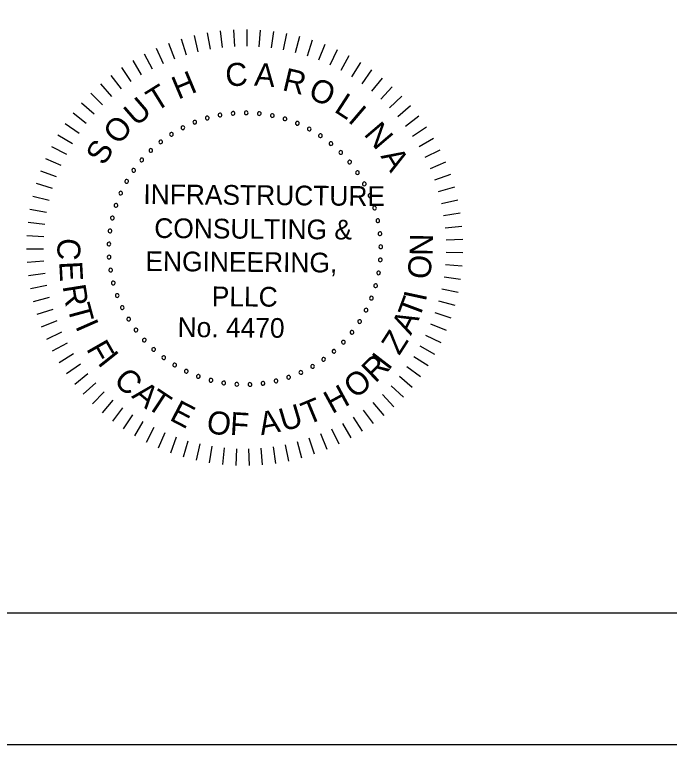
# Model space of a CAD drawing. Extents: x 2799.7 to 2896, y 515.2 to 573.9.
# Drawn here: x 2867.59 to 2874.21, y 515.22 to 522.61 of the extents above; entities that cross this region are included whole.
import ezdxf

# ---------------------------------------------------------------- set-up
doc = ezdxf.new("R2010")
doc.units = 0
for name, color, linetype in [('BR_BORDER LINES', 7, 'Continuous'), ('BR_TEXT', 7, 'Continuous'), ('Level 31', 7, 'Continuous')]:
    doc.layers.add(name, color=color, linetype=linetype)

msp = doc.modelspace()

# ---------------------------------------------------------------- linework, layer by layer
at = {"layer": 'BR_BORDER LINES'}
msp.add_line((2804.5816, 516.5558), (2894.3589, 516.5558), dxfattribs=at)
at = {"layer": 'BR_TEXT'}
for p, q in [((2869.6661, 522.4445), (2869.6854, 522.2758)), ((2869.8003, 522.4555), (2869.8093, 522.286)), ((2869.9349, 522.4584), (2869.9335, 522.2886)), ((2870.0694, 522.453), (2870.0577, 522.2836)), ((2870.2034, 522.4394), (2870.1813, 522.2711)), ((2869.2711, 522.3628), (2869.3208, 522.2004)), ((2869.4011, 522.3981), (2869.4407, 522.233)), ((2869.5329, 522.4253), (2869.5624, 522.2581)), ((2870.3362, 522.4177), (2870.304, 522.251)), ((2870.4675, 522.3879), (2870.4251, 522.2235)), ((2869.1436, 522.3197), (2869.2031, 522.1606)), ((2870.5968, 522.3502), (2870.5444, 522.1887)), ((2870.7235, 522.3047), (2870.6614, 522.1467)), ((2869.0189, 522.2689), (2869.088, 522.1137)), ((2870.8471, 522.2515), (2870.7755, 522.0976)), ((2868.78, 522.1449), (2868.8674, 521.9994)), ((2868.8976, 522.2105), (2868.976, 522.0599)), ((2870.9673, 522.1909), (2870.8865, 522.0416)), ((2868.6667, 522.0723), (2868.7628, 521.9323)), ((2871.0836, 522.1231), (2870.9938, 521.979)), ((2871.1956, 522.0483), (2871.0972, 521.9099)), ((2868.558, 521.9929), (2868.6625, 521.859)), ((2871.3027, 521.9668), (2871.1961, 521.8347)), ((2868.4544, 521.9069), (2868.5668, 521.7797)), ((2871.4048, 521.879), (2871.2902, 521.7536)), ((2868.3561, 521.8149), (2868.4761, 521.6947)), ((2871.5012, 521.7851), (2871.3793, 521.6669)), ((2868.2637, 521.717), (2868.3908, 521.6044)), ((2871.5918, 521.6855), (2871.4628, 521.575)), ((2868.1774, 521.6137), (2868.3111, 521.509)), ((2871.6761, 521.5805), (2871.5407, 521.4781)), ((2868.0976, 521.5053), (2868.2374, 521.409)), ((2871.7538, 521.4706), (2871.6124, 521.3766)), ((2868.0245, 521.3922), (2868.17, 521.3046)), ((2871.8248, 521.3562), (2871.6779, 521.271)), ((2867.9585, 521.2749), (2868.109, 521.1963)), ((2871.8886, 521.2376), (2871.7368, 521.1616)), ((2867.8997, 521.1538), (2868.0547, 521.0845)), ((2871.945, 521.1154), (2871.7889, 521.0487)), ((2867.8484, 521.0293), (2868.0074, 520.9696)), ((2871.9939, 520.99), (2871.834, 520.933)), ((2867.8048, 520.9019), (2867.9671, 520.8521)), ((2872.0351, 520.8618), (2871.872, 520.8146)), ((2867.7691, 520.7721), (2867.9341, 520.7323)), ((2872.0684, 520.7314), (2871.9027, 520.6942)), ((2867.7413, 520.6404), (2867.9085, 520.6107)), ((2872.0936, 520.5991), (2871.926, 520.5722)), ((2867.7216, 520.5072), (2867.8903, 520.4877)), ((2872.1108, 520.4656), (2871.9418, 520.4489)), ((2867.7101, 520.3731), (2867.8797, 520.3639)), ((2872.1198, 520.3313), (2871.9501, 520.3249)), ((2867.7068, 520.2385), (2867.8766, 520.2397)), ((2872.1206, 520.1967), (2871.9508, 520.2006)), ((2867.7117, 520.104), (2867.8811, 520.1155)), ((2872.1131, 520.0622), (2871.9439, 520.0766)), ((2867.7247, 519.97), (2867.8931, 519.9918)), ((2872.0975, 519.9285), (2871.9295, 519.9531)), ((2867.746, 519.837), (2867.9127, 519.8691)), ((2872.0738, 519.796), (2871.9076, 519.8308)), ((2867.7752, 519.7056), (2867.9397, 519.7478)), ((2872.042, 519.6652), (2871.8783, 519.7101)), ((2867.8125, 519.5763), (2867.9741, 519.6284)), ((2872.0023, 519.5365), (2871.8416, 519.5913)), ((2867.8575, 519.4494), (2868.0157, 519.5113)), ((2871.9549, 519.4106), (2871.7978, 519.475)), ((2867.9103, 519.3255), (2868.0643, 519.3969)), ((2871.8998, 519.2877), (2871.747, 519.3616)), ((2867.9704, 519.2051), (2868.1198, 519.2857)), ((2871.8374, 519.1684), (2871.6893, 519.2515)), ((2868.0378, 519.0885), (2868.182, 519.1782)), ((2871.7678, 519.0532), (2871.6251, 519.1452)), ((2868.1122, 518.9763), (2868.2507, 519.0746)), ((2871.6913, 518.9424), (2871.5545, 519.0429)), ((2868.1933, 518.8688), (2868.3255, 518.9753)), ((2871.6082, 518.8365), (2871.4778, 518.9451)), ((2868.2807, 518.7665), (2868.4062, 518.8809)), ((2871.5188, 518.7358), (2871.3952, 518.8522)), ((2868.3743, 518.6697), (2868.4926, 518.7915)), ((2871.4234, 518.6408), (2871.3072, 518.7645)), ((2868.4736, 518.5788), (2868.5842, 518.7076)), ((2871.3225, 518.5518), (2871.214, 518.6824)), ((2868.5782, 518.4941), (2868.6808, 518.6294)), ((2871.2162, 518.4691), (2871.1159, 518.606)), ((2868.6878, 518.4159), (2868.782, 518.5572)), ((2871.1052, 518.393), (2871.0134, 518.5358)), ((2868.802, 518.3446), (2868.8873, 518.4913)), ((2870.9897, 518.3238), (2870.9067, 518.472)), ((2868.9203, 518.2803), (2868.9965, 518.432)), ((2869.0423, 518.2234), (2869.1091, 518.3795)), ((2870.8702, 518.2618), (2870.7964, 518.4148)), ((2869.1675, 518.174), (2869.2248, 518.3339)), ((2870.6209, 518.1603), (2870.5664, 518.321)), ((2870.7471, 518.2072), (2870.6828, 518.3644)), ((2869.2956, 518.1324), (2869.3429, 518.2954)), ((2869.4259, 518.0986), (2869.4632, 518.2643)), ((2869.558, 518.0729), (2869.5852, 518.2405)), ((2870.2286, 518.0665), (2870.2042, 518.2345)), ((2870.3612, 518.0898), (2870.3266, 518.256)), ((2870.4922, 518.1211), (2870.4475, 518.2849)), ((2869.6915, 518.0552), (2869.7084, 518.2242)), ((2869.8258, 518.0458), (2869.8323, 518.2154)), ((2869.9604, 518.0445), (2869.9566, 518.2142)), ((2870.0948, 518.0514), (2870.0807, 518.2206))]:
    msp.add_line(p, q, dxfattribs=at)
for centre, start, end in [((2869.7956, 521.6102), 5.06529, 185.06529), ((2869.9284, 521.6153), 359.52683, 179.52683), ((2870.0611, 521.6075), 353.98837, 173.98837), ((2869.5346, 521.5619), 16.14222, 196.14222), ((2869.5346, 521.5619), 196.14222, 16.14222), ((2869.664, 521.5924), 10.60376, 190.60376), ((2869.664, 521.5924), 190.60376, 10.60376), ((2869.7956, 521.6102), 185.06529, 5.06529), ((2869.9284, 521.6153), 179.52683, 359.52683), ((2870.0611, 521.6075), 173.98837, 353.98837), ((2870.1924, 521.587), 168.44991, 348.44991), ((2870.1924, 521.587), 348.44991, 168.44991), ((2870.3211, 521.5538), 162.91145, 342.91145), ((2870.3211, 521.5538), 342.91145, 162.91145), ((2869.2878, 521.4643), 27.21914, 207.21914), ((2869.4088, 521.5191), 21.68068, 201.68068), ((2869.4088, 521.5191), 201.68068, 21.68068), ((2870.446, 521.5085), 157.37299, 337.37299), ((2870.446, 521.5085), 337.37299, 157.37299), ((2869.1725, 521.3981), 32.7576, 212.7576), ((2869.1725, 521.3981), 212.7576, 32.7576), ((2869.2878, 521.4643), 207.21914, 27.21914), ((2870.5659, 521.4512), 151.83453, 331.83453), ((2870.5659, 521.4512), 331.83453, 151.83453), ((2869.0642, 521.3211), 38.29606, 218.29606), ((2869.0642, 521.3211), 218.29606, 38.29606), ((2870.6797, 521.3827), 146.29606, 326.29606), ((2870.6797, 521.3827), 326.29606, 146.29606), ((2870.7864, 521.3035), 140.7576, 320.7576), ((2870.7864, 521.3035), 320.7576, 140.7576), ((2868.9639, 521.234), 43.83453, 223.83453), ((2868.9639, 521.234), 223.83453, 43.83453), ((2870.885, 521.2144), 135.21914, 315.21914), ((2870.885, 521.2144), 315.21914, 135.21914), ((2868.8724, 521.1377), 49.37299, 229.37299), ((2868.8724, 521.1377), 229.37299, 49.37299), ((2870.9745, 521.1161), 129.68068, 309.68068), ((2870.9745, 521.1161), 309.68068, 129.68068), ((2868.7906, 521.0329), 54.91145, 234.91145), ((2868.7906, 521.0329), 234.91145, 54.91145), ((2871.0541, 521.0097), 124.14222, 304.14222), ((2871.0541, 521.0097), 304.14222, 124.14222), ((2868.7194, 520.9208), 60.44991, 240.44991), ((2868.7194, 520.9208), 240.44991, 60.44991), ((2871.123, 520.8961), 118.60376, 298.60376), ((2871.123, 520.8961), 298.60376, 118.60376), ((2868.6592, 520.8022), 65.98837, 245.98837), ((2868.6592, 520.8022), 245.98837, 65.98837), ((2871.1807, 520.7764), 113.06529, 293.06529), ((2871.1807, 520.7764), 293.06529, 113.06529), ((2868.6109, 520.6785), 71.52683, 251.52683), ((2868.6109, 520.6785), 251.52683, 71.52683), ((2871.2265, 520.6517), 107.52683, 287.52683), ((2871.2265, 520.6517), 287.52683, 107.52683), ((2868.5746, 520.5506), 77.06529, 257.06529), ((2868.5746, 520.5506), 257.06529, 77.06529), ((2871.2601, 520.5231), 101.98837, 281.98837), ((2871.2601, 520.5231), 281.98837, 101.98837), ((2868.5509, 520.4199), 82.60376, 262.60376), ((2868.5509, 520.4199), 262.60376, 82.60376), ((2871.2812, 520.3919), 96.44991, 276.44991), ((2871.2812, 520.3919), 276.44991, 96.44991), ((2868.5399, 520.2875), 88.14222, 268.14222), ((2868.5399, 520.2875), 268.14222, 88.14222), ((2871.2894, 520.2593), 90.91145, 270.91145), ((2871.2894, 520.2593), 270.91145, 90.91145), ((2868.5418, 520.1546), 93.68068, 273.68068), ((2868.5418, 520.1546), 273.68068, 93.68068), ((2871.2849, 520.1265), 85.37299, 265.37299), ((2871.2849, 520.1265), 265.37299, 85.37299), ((2868.5565, 520.0225), 99.21914, 279.21914), ((2868.5565, 520.0225), 279.21914, 99.21914), ((2871.2675, 519.9947), 79.83453, 259.83453), ((2871.2675, 519.9947), 259.83453, 79.83453), ((2868.5838, 519.8925), 104.7576, 284.7576), ((2868.5838, 519.8925), 284.7576, 104.7576), ((2871.2375, 519.8653), 74.29606, 254.29606), ((2871.2375, 519.8653), 254.29606, 74.29606), ((2868.6236, 519.7657), 110.29606, 290.29606), ((2868.6236, 519.7657), 290.29606, 110.29606), ((2871.1951, 519.7393), 68.7576, 248.7576), ((2871.1951, 519.7393), 248.7576, 68.7576), ((2868.6754, 519.6433), 115.83453, 295.83453), ((2868.6754, 519.6433), 295.83453, 115.83453), ((2871.1408, 519.6181), 63.21914, 243.21914), ((2871.1408, 519.6181), 243.21914, 63.21914), ((2868.7388, 519.5265), 121.37299, 301.37299), ((2868.7388, 519.5265), 301.37299, 121.37299), ((2871.0751, 519.5026), 57.68068, 237.68068), ((2871.0751, 519.5026), 237.68068, 57.68068), ((2868.8131, 519.4164), 126.91145, 306.91145), ((2868.8131, 519.4164), 306.91145, 126.91145), ((2870.9985, 519.394), 52.14222, 232.14222), ((2870.9985, 519.394), 232.14222, 52.14222), ((2868.8978, 519.314), 132.44991, 312.44991), ((2868.8978, 519.314), 312.44991, 132.44991), ((2870.9117, 519.2933), 46.60376, 226.60376), ((2870.9117, 519.2933), 226.60376, 46.60376), ((2868.9919, 519.2202), 137.98837, 317.98837), ((2868.9919, 519.2202), 317.98837, 137.98837), ((2870.8157, 519.2015), 41.06529, 221.06529), ((2870.8157, 519.2015), 221.06529, 41.06529), ((2869.0947, 519.1359), 143.52683, 323.52683), ((2869.0947, 519.1359), 323.52683, 143.52683), ((2870.7112, 519.1193), 35.52683, 215.52683), ((2870.7112, 519.1193), 215.52683, 35.52683), ((2869.2051, 519.0619), 149.06529, 329.06529), ((2869.2051, 519.0619), 329.06529, 149.06529), ((2870.5994, 519.0477), 29.98837, 209.98837), ((2870.5994, 519.0477), 209.98837, 29.98837), ((2869.3221, 518.999), 154.60376, 334.60376), ((2869.3221, 518.999), 334.60376, 154.60376), ((2869.4446, 518.9476), 340.14222, 160.14222), ((2870.4811, 518.9871), 24.44991, 204.44991), ((2870.4811, 518.9871), 204.44991, 24.44991), ((2869.4446, 518.9476), 160.14222, 340.14222), ((2869.5716, 518.9083), 165.68068, 345.68068), ((2869.5716, 518.9083), 345.68068, 165.68068), ((2869.7017, 518.8815), 351.21914, 171.21914), ((2870.0991, 518.8774), 7.83453, 187.83453), ((2870.2298, 518.9016), 13.37299, 193.37299), ((2870.2298, 518.9016), 193.37299, 13.37299), ((2870.3575, 518.9383), 18.91145, 198.91145), ((2870.3575, 518.9383), 198.91145, 18.91145), ((2869.7017, 518.8815), 171.21914, 351.21914), ((2869.8338, 518.8673), 176.7576, 356.7576), ((2869.8338, 518.8673), 356.7576, 176.7576), ((2869.9667, 518.8659), 2.29606, 182.29606), ((2869.9667, 518.8659), 182.29606, 2.29606), ((2870.0991, 518.8774), 187.83453, 7.83453)]:
    msp.add_arc(centre, 0.0187, start, end, dxfattribs=at)
at = {"layer": 'Level 31'}
msp.add_lwpolyline([(2799.6927, 573.89), (2799.6927, 515.2226), (2895.6939, 515.2226), (2895.6939, 573.89)], dxfattribs=at)

# ---------------------------------------------------------------- texts
at = {"layer": 'BR_TEXT'}
for s, height, rotation, p in [('C', 0.2325, 4.72812, (2869.7271, 521.8781)), ('A', 0.2325, 355.69809, (2870.0057, 521.8913)), ('H', 0.2325, 22.78817, (2869.2395, 521.7464)), ('R', 0.2325, 346.66807, (2870.2838, 521.846)), ('O', 0.2325, 337.63804, (2870.5444, 521.7665)), ('T', 0.2325, 31.81819, (2869.0133, 521.6193)), ('U', 0.2325, 40.84822, (2868.8178, 521.4697)), ('L', 0.2325, 327.10802, (2870.808, 521.632)), ('I', 0.2325, 319.578, (2870.9481, 521.5311)), ('O', 0.2325, 49.87824, (2868.6392, 521.2803)), ('N', 0.2325, 310.54797, (2871.1103, 521.3957)), ('S', 0.2325, 58.90827, (2868.4913, 521.0718)), ('A', 0.2325, 301.51795, (2871.2838, 521.176)), ('INFRASTRUCTURE', 0.199393, 359.52683, (2868.8877, 520.6918)), ('CONSULTING &', 0.199393, 359.52683, (2868.9978, 520.3488)), ('N', 0.2325, 89.20849, (2871.8153, 520.166)), ('C', 0.2325, 267.02504, (2868.0247, 520.352)), ('ENGINEERING,', 0.199393, 359.52683, (2868.9082, 520.0143)), ('O', 0.2325, 83.20849, (2871.7857, 519.9221)), ('E', 0.2325, 273.02504, (2868.0364, 520.1078)), ('R', 0.2325, 279.02504, (2868.0705, 519.8617)), ('PLLC', 0.19939, 359.52683, (2869.5794, 519.6581)), ('I', 0.2325, 77.90926, (2871.7443, 519.6973)), ('T', 0.2325, 285.02504, (2868.1169, 519.6516)), ('T', 0.2325, 69.39539, (2871.6758, 519.5174)), ('A', 0.2325, 63.39539, (2871.5937, 519.3564)), ('I', 0.2325, 293.77127, (2868.1961, 519.4567)), ('No. 4470', 0.19939, 359.52683, (2869.234, 519.3464)), ('Z', 0.2325, 57.39539, (2871.4768, 519.1528)), ('F', 0.2325, 299.77127, (2868.3059, 519.2272)), ('I', 0.2325, 308.52683, (2868.4182, 519.0836)), ('I', 0.2325, 52.33388, (2871.3673, 518.999)), ('R', 0.2325, 44.52683, (2871.2356, 518.8729)), ('C', 0.2325, 314.52683, (2868.5765, 518.8966)), ('O', 0.2325, 38.52683, (2871.0314, 518.713)), ('A', 0.2325, 320.52683, (2868.7609, 518.7404)), ('T', 0.2325, 326.52683, (2868.9061, 518.6378)), ('H', 0.2325, 28.52683, (2870.7964, 518.5637)), ('E', 0.2325, 332.52683, (2869.1423, 518.5103)), ('T', 0.2325, 22.52683, (2870.548, 518.4523)), ('O', 0.2325, 350.52683, (2869.516, 518.38)), ('A', 0.2325, 10.52683, (2870.0796, 518.3513)), ('U', 0.2325, 16.52683, (2870.3033, 518.3873)), ('F', 0.2325, 356.52683, (2869.7599, 518.3557))]:
    msp.add_text(s, height=height, rotation=rotation, dxfattribs=at).set_placement(p)

doc.saveas('drawing.dxf')
